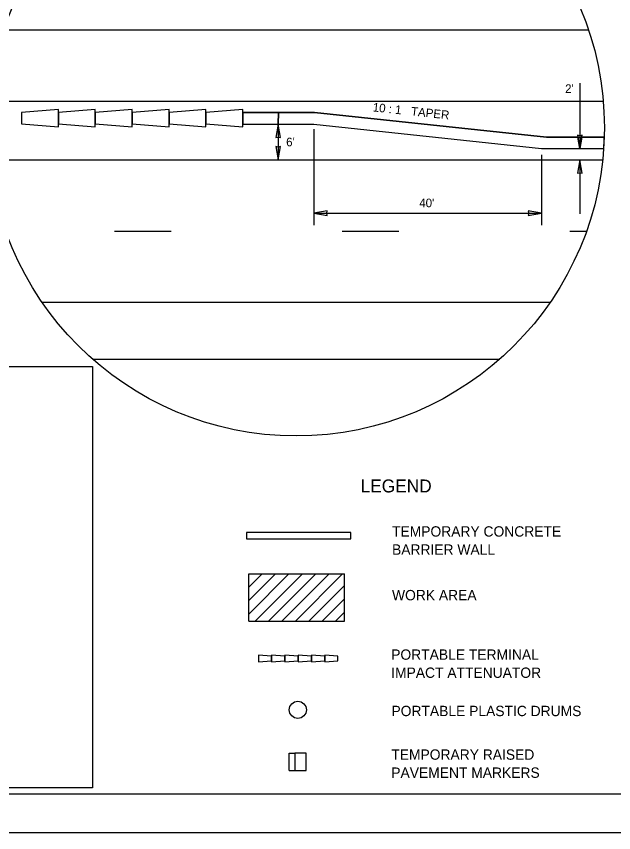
# Model space of a CAD drawing. Extents: x -2541 to -1265, y -5743 to -4928.
# Drawn here: x -1696.1 to -1419, y -5742.8 to -5364.1 of the extents above; entities that cross this region are included whole.
import ezdxf

# ---------------------------------------------------------------- set-up
doc = ezdxf.new("R2010")
doc.units = 0
for name, color, linetype in [('Level 42', 7, 'Continuous'), ('Level 45', 7, 'Continuous'), ('Level 46', 7, 'Continuous'), ('Level 47', 7, 'Continuous'), ('Level 48', 7, 'Continuous'), ('Level 49', 7, 'Continuous'), ('Level 50', 7, 'Continuous'), ('TR_WZ_TC_Edge Lines', 7, 'Continuous')]:
    doc.layers.add(name, color=color, linetype=linetype)

msp = doc.modelspace()

# ---------------------------------------------------------------- linework, layer by layer
at = {"layer": 'Level 42'}
msp.add_line((-1278.83, -5724.86), (-2472.96, -5724.86), dxfattribs=at)
msp.add_lwpolyline([(-2472.96, -4943.66), (-1412.92, -4943.66), (-1412.92, -5724.9), (-2472.96, -5724.9)], close=True, dxfattribs=at)
at = {"layer": 'Level 45'}
for p, q in [((-1708.54, -5430.68), (-1424.11, -5430.68)), ((-1569.53, -5713.9), (-1569.53, -5705.98)), ((-1569.53, -5705.98), (-1566.89, -5705.98)), ((-1561.61, -5705.98), (-1566.89, -5705.98)), ((-1566.89, -5705.98), (-1566.89, -5713.9)), ((-1561.61, -5713.9), (-1561.61, -5705.98)), ((-1569.53, -5713.9), (-1566.89, -5713.9)), ((-1566.89, -5713.9), (-1561.61, -5713.9))]:
    msp.add_line(p, q, dxfattribs=at)
at = {"layer": 'Level 46'}
for p, q in [((-1434.7, -5395.15), (-1434.7, -5425.4)), ((-1574.59, -5414.18), (-1574.59, -5430.68)), ((-1558.09, -5416.51), (-1558.09, -5460.93)), ((-1452.49, -5428.39), (-1452.49, -5460.93)), ((-1434.7, -5430.68), (-1434.7, -5455.69)), ((-1558.09, -5455.44), (-1452.49, -5455.44)), ((-1650.63, -5463.68), (-1624.23, -5463.68)), ((-1545.03, -5463.68), (-1518.63, -5463.68)), ((-1439.43, -5463.68), (-1431.6, -5463.68)), ((-1684.22, -5496.68), (-1448.43, -5496.68)), ((-1660.81, -5523.08), (-1471.83, -5523.08))]:
    msp.add_line(p, q, dxfattribs=at)
msp.add_circle((-1566.32, -5415.75), 143, dxfattribs=at)
at = {"layer": 'Level 47'}
for p, q in [((-1588.3, -5644.63), (-1588.3, -5622.7)), ((-1588.3, -5641.37), (-1569.63, -5622.7)), ((-1588.3, -5635.15), (-1575.85, -5622.7)), ((-1588.3, -5628.93), (-1582.07, -5622.7)), ((-1588.3, -5622.7), (-1543.89, -5622.7)), ((-1585.33, -5644.63), (-1563.41, -5622.7)), ((-1579.11, -5644.63), (-1557.18, -5622.7)), ((-1572.89, -5644.63), (-1550.96, -5622.7)), ((-1566.66, -5644.63), (-1544.74, -5622.7)), ((-1543.89, -5644.63), (-1543.89, -5622.7)), ((-1560.44, -5644.63), (-1543.89, -5628.07)), ((-1554.22, -5644.63), (-1543.89, -5634.3)), ((-1548, -5644.63), (-1543.89, -5640.52)), ((-1588.3, -5644.63), (-1543.89, -5644.63))]:
    msp.add_line(p, q, dxfattribs=at)
at = {"layer": 'Level 48'}
for p, q in [((-1591.09, -5414.18), (-1591.09, -5408.68)), ((-1591.09, -5408.68), (-1557.8, -5408.68)), ((-1591.09, -5408.68), (-1591.09, -5414.18)), ((-1574.44, -5408.68), (-1591.09, -5408.68)), ((-1574.44, -5408.68), (-1574.59, -5414.18)), ((-1574.59, -5414.18), (-1574.44, -5408.68)), ((-1557.8, -5408.68), (-1574.44, -5408.68)), ((-1557.8, -5408.68), (-1450.13, -5420.12)), ((-1450.13, -5420.12), (-1557.8, -5408.68)), ((-1591.09, -5414.18), (-1558.09, -5414.18)), ((-1591.09, -5414.18), (-1574.59, -5414.18)), ((-1574.59, -5414.18), (-1558.09, -5414.18)), ((-1558.09, -5414.18), (-1452.49, -5425.4)), ((-1558.09, -5414.18), (-1452.49, -5425.4)), ((-1450.13, -5420.12), (-1423.39, -5420.12)), ((-1435.63, -5420.12), (-1450.13, -5420.12)), ((-1434.7, -5425.4), (-1435.63, -5420.12)), ((-1433.77, -5420.12), (-1434.7, -5425.4)), ((-1423.39, -5420.12), (-1433.77, -5420.12)), ((-1452.49, -5425.4), (-1423.65, -5425.4)), ((-1452.49, -5425.4), (-1434.7, -5425.4)), ((-1434.7, -5425.4), (-1423.65, -5425.4)), ((-1541.02, -5603.51), (-1589.35, -5603.51)), ((-1589.35, -5603.51), (-1589.35, -5606.44)), ((-1589.35, -5606.44), (-1541.02, -5606.44))]:
    msp.add_line(p, q, dxfattribs=at)
msp.add_lwpolyline([(-1541.02, -5606.44), (-1541.02, -5603.51)], dxfattribs=at)
msp.add_arc((-1566.32, -5415.75), 143, 356.1291, 358.2473, dxfattribs=at)
at = {"layer": 'Level 49'}
for p, q in [((-1574.59, -5414.18), (-1575.67, -5420.33)), ((-1573.51, -5420.33), (-1574.59, -5414.18)), ((-1434.7, -5419.45), (-1435.78, -5419.26)), ((-1435.78, -5419.26), (-1434.7, -5425.4)), ((-1434.7, -5425.4), (-1433.61, -5419.26)), ((-1433.61, -5419.26), (-1434.7, -5419.45)), ((-1575.67, -5420.33), (-1574.59, -5420.14)), ((-1574.59, -5420.14), (-1573.51, -5420.33)), ((-1574.59, -5424.73), (-1575.67, -5424.54)), ((-1575.67, -5424.54), (-1574.59, -5430.68)), ((-1574.59, -5430.68), (-1573.51, -5424.54)), ((-1573.51, -5424.54), (-1574.59, -5424.73)), ((-1434.7, -5430.68), (-1435.78, -5436.83)), ((-1433.61, -5436.83), (-1434.7, -5430.68)), ((-1435.78, -5436.83), (-1434.7, -5436.64)), ((-1434.7, -5436.64), (-1433.61, -5436.83)), ((-1551.94, -5454.35), (-1558.09, -5455.44)), ((-1558.09, -5455.44), (-1551.94, -5456.52)), ((-1552.13, -5455.44), (-1551.94, -5454.35)), ((-1551.94, -5456.52), (-1552.13, -5455.44)), ((-1452.49, -5455.44), (-1458.63, -5454.35)), ((-1458.63, -5454.35), (-1458.44, -5455.44)), ((-1458.44, -5455.44), (-1458.63, -5456.52)), ((-1458.63, -5456.52), (-1452.49, -5455.44))]:
    msp.add_line(p, q, dxfattribs=at)
at = {"layer": 'Level 50'}
for p, q in [((-1676.56, -5407.37), (-1693.65, -5408.69)), ((-1676.56, -5415.29), (-1676.56, -5407.37)), ((-1659.47, -5407.37), (-1676.56, -5408.69)), ((-1659.47, -5415.29), (-1659.47, -5407.37)), ((-1642.37, -5407.37), (-1659.47, -5408.69)), ((-1642.37, -5415.29), (-1642.37, -5407.37)), ((-1625.28, -5407.37), (-1642.37, -5408.69)), ((-1625.28, -5415.29), (-1625.28, -5407.37)), ((-1608.18, -5407.37), (-1625.28, -5408.69)), ((-1608.18, -5415.29), (-1608.18, -5407.37)), ((-1591.09, -5407.37), (-1608.18, -5408.69)), ((-1591.09, -5415.29), (-1591.09, -5407.37)), ((-1693.65, -5408.69), (-1693.65, -5413.97)), ((-1676.56, -5408.69), (-1676.56, -5413.97)), ((-1659.47, -5408.69), (-1659.47, -5413.97)), ((-1659.46, -5411.33), (-1659.46, -5411.33)), ((-1642.37, -5408.69), (-1642.37, -5413.97)), ((-1625.28, -5408.69), (-1625.28, -5413.97)), ((-1608.18, -5408.69), (-1608.18, -5413.97)), ((-1693.65, -5413.97), (-1676.56, -5415.29)), ((-1676.56, -5413.97), (-1659.47, -5415.29)), ((-1659.47, -5413.97), (-1642.37, -5415.29)), ((-1642.37, -5413.97), (-1625.28, -5415.29)), ((-1625.28, -5413.97), (-1608.18, -5415.29)), ((-1608.18, -5413.97), (-1591.09, -5415.29)), ((-1577.68, -5660.95), (-1583.83, -5660.42)), ((-1583.83, -5660.42), (-1583.83, -5663.59)), ((-1571.53, -5660.95), (-1577.68, -5660.42)), ((-1577.68, -5660.42), (-1577.68, -5663.59)), ((-1577.68, -5663.06), (-1577.68, -5660.95)), ((-1565.37, -5660.95), (-1571.53, -5660.42)), ((-1571.53, -5660.42), (-1571.53, -5663.59)), ((-1571.53, -5663.06), (-1571.53, -5660.95)), ((-1559.22, -5660.95), (-1565.37, -5660.42)), ((-1565.37, -5660.42), (-1565.37, -5663.59)), ((-1565.37, -5663.06), (-1565.37, -5660.95)), ((-1553.06, -5660.95), (-1559.22, -5660.42)), ((-1559.22, -5660.42), (-1559.22, -5663.59)), ((-1559.22, -5663.06), (-1559.22, -5660.95)), ((-1546.91, -5660.95), (-1553.06, -5660.42)), ((-1553.06, -5660.42), (-1553.06, -5663.59)), ((-1553.06, -5663.06), (-1553.06, -5660.95)), ((-1546.91, -5663.06), (-1546.91, -5660.95)), ((-1583.83, -5663.59), (-1577.68, -5663.06)), ((-1577.68, -5663.59), (-1571.53, -5663.06)), ((-1571.53, -5663.59), (-1565.37, -5663.06)), ((-1565.37, -5663.59), (-1559.22, -5663.06)), ((-1559.22, -5662), (-1559.22, -5662)), ((-1559.22, -5663.59), (-1553.06, -5663.06)), ((-1553.06, -5663.59), (-1546.91, -5663.06))]:
    msp.add_line(p, q, dxfattribs=at)
msp.add_lwpolyline([(-2541.13, -4927.7), (-1265.77, -4927.7), (-1265.77, -5742.8), (-2541.13, -5742.8)], close=True, dxfattribs=at)
msp.add_circle((-1565.53, -5685.81), 3.96, dxfattribs=at)
at = {"layer": 'TR_WZ_TC_Edge Lines'}
for p, q in [((-1701.94, -5370.4), (-1430.7, -5370.4)), ((-1708.79, -5403.4), (-1424.11, -5403.4))]:
    msp.add_line(p, q, dxfattribs=at)
msp.add_lwpolyline([(-2036.29, -5526.51), (-1660.76, -5526.51), (-1660.76, -5722.02), (-2036.29, -5722.02)], close=True, dxfattribs=at)

# ---------------------------------------------------------------- texts
at = {"layer": 'Level 42'}
for s, height, p in [("2'", 4, (-1441.54, -5399.64)), ("6'", 4, (-1570.95, -5424.39)), ("40'", 4, (-1509.21, -5452.66)), ('LEGEND', 6, (-1536.43, -5584.95)), ('TEMPORARY CONCRETE', 4.8, (-1521.83, -5605.45)), ('BARRIER WALL', 4.8, (-1521.83, -5613.85)), ('WORK AREA', 4.8, (-1521.84, -5635)), ('PORTABLE TERMINAL', 4.8, (-1522.21, -5662.58)), ('IMPACT ATTENUATOR', 4.8, (-1522.21, -5670.98)), ('PORTABLE PLASTIC DRUMS', 4.8, (-1522.09, -5688.74)), ('TEMPORARY RAISED', 4.8, (-1522.17, -5708.96)), ('PAVEMENT MARKERS', 4.8, (-1522.17, -5717.36))]:
    msp.add_text(s, height=height, dxfattribs=at).set_placement(p)
msp.add_text('10 : 1   TAPER', height=4, rotation=353.9351, dxfattribs=at).set_placement((-1530.94, -5408.16))

doc.saveas('drawing.dxf')
